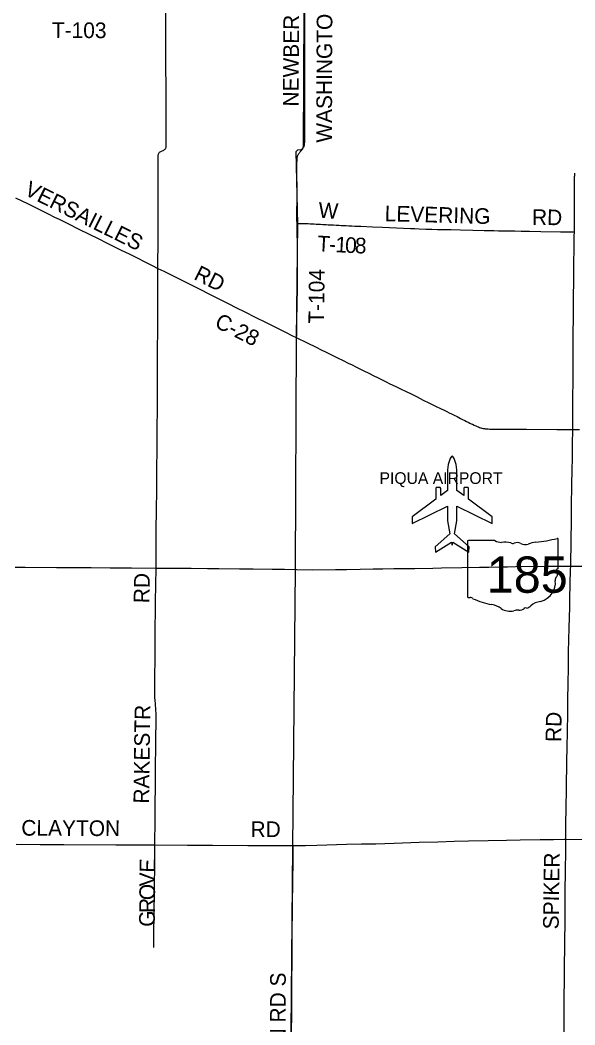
# Model space of a CAD drawing. Extents: x -87 to 2145, y -2128 to 440.
# Drawn here: x 168 to 221.2, y -563.5 to -467.2 of the extents above; entities that cross this region are included whole.
import ezdxf

# ---------------------------------------------------------------- set-up
doc = ezdxf.new("R2010")
doc.units = 0
for name, color, linetype in [('GM_X_Airport_Class_2', 7, 'Continuous'), ('GM_X_Airport_Location_Class_2', 7, 'Continuous'), ('GM_X_Airport_Text_Class_2', 7, 'Continuous'), ('GM_X_County_Road', 7, 'Continuous'), ('GM_X_County_Road_Text', 7, 'Continuous'), ('GM_X_State_Location', 7, 'Continuous'), ('GM_X_State_Route', 7, 'Continuous'), ('GM_X_State_Shield', 7, 'Continuous'), ('GM_X_Township', 7, 'Continuous'), ('GM_X_Township_Road', 7, 'Continuous'), ('GM_X_Township_Road_Text', 7, 'Continuous')]:
    doc.layers.add(name, color=color, linetype=linetype)

msp = doc.modelspace()

# ---------------------------------------------------------------- linework, layer by layer
at = {"layer": 'GM_X_Airport_Class_2'}
msp.add_lwpolyline([(207.876, -513.109), (205.594, -514.797), (205.594, -515.444), (208.989, -513.771), (208.989, -515.18), (209.214, -516.427), (207.817, -517.68), (207.839, -518.196), (209.369, -517.248), (209.44, -517.525), (209.51, -517.248), (211.041, -518.196), (211.062, -517.68), (209.665, -516.427), (209.891, -515.18), (209.891, -513.771), (213.286, -515.444), (213.286, -514.797), (211.004, -513.109), (211.004, -512.102), (210.968, -511.98), (210.58, -511.98), (210.544, -512.102), (210.544, -512.77), (209.891, -512.286), (209.891, -512.286), (209.891, -510.297), (209.825, -509.771), (209.77, -509.584), (209.635, -509.2), (209.511, -509.03), (209.44, -509), (209.369, -509.03), (209.244, -509.2), (209.109, -509.584), (209.055, -509.771), (208.989, -510.297), (208.989, -512.286), (208.335, -512.77), (208.335, -512.102), (208.3, -511.98), (207.911, -511.98), (207.876, -512.102)], close=True, dxfattribs=at)
at = {"layer": 'GM_X_Airport_Location_Class_2'}
msp.add_line((209.44, -513.913), (209.44, -513.913), dxfattribs=at)
at = {"layer": 'GM_X_County_Road'}
for points in [[(181.247, -490.98), (181.253, -488.079), (181.261, -485.553), (181.257, -484.307), (181.26, -482.912), (181.256, -481.01), (181.263, -480.221), (181.271, -480.121), (181.284, -480.054), (181.306, -479.989), (181.337, -479.926), (181.366, -479.883), (181.402, -479.844), (181.443, -479.811), (181.531, -479.761), (181.797, -479.634), (181.878, -479.584), (181.929, -479.535), (181.959, -479.494), (181.983, -479.452), (181.998, -479.418), (182.02, -479.336), (182.032, -479.258), (182.042, -479.112), (182.043, -478.916), (182.029, -476.881), (182.021, -475.733), (182.019, -474.65), (182.018, -473.322), (182.014, -471.878), (182.01, -469.992), (182.003, -467.974), (182.002, -466.354)], [(167.595, -484.197), (168.815, -484.802), (169.506, -485.143), (170.713, -485.737), (171.345, -486.051), (171.77, -486.265), (172.604, -486.687), (173.677, -487.218), (175.573, -488.157), (176.323, -488.529), (177.13, -488.931), (177.66, -489.192), (178.543, -489.627), (180.684, -490.7), (181.247, -490.98)], [(181.057, -519.724), (181.064, -519.155), (181.086, -517.073), (181.085, -515.647), (181.098, -514.58), (181.129, -511.842), (181.151, -509.874), (181.163, -508.677), (181.182, -506.43), (181.194, -504.331), (181.2, -502.839), (181.203, -501.461), (181.21, -499.608), (181.212, -498.509), (181.216, -497.148), (181.226, -494.999), (181.247, -490.98)], [(181.247, -490.98), (181.8, -491.255), (183.899, -492.304), (185.322, -493.015), (186.127, -493.423), (186.818, -493.763), (187.975, -494.348), (188.767, -494.745), (189.512, -495.125), (190.627, -495.682), (191.536, -496.138), (191.932, -496.336), (192.636, -496.689), (193.46, -497.095), (194.077, -497.4), (194.5, -497.597)], [(194.5, -497.597), (195.532, -498.122), (196.39, -498.544), (196.876, -498.783), (197.358, -499.019), (197.927, -499.299), (198.439, -499.551), (198.999, -499.826), (199.465, -500.059), (199.841, -500.243), (200.19, -500.414), (200.524, -500.582), (200.919, -500.775), (201.521, -501.071), (201.939, -501.278), (202.27, -501.444), (202.731, -501.671), (203.116, -501.86), (203.477, -502.037), (203.981, -502.281), (204.496, -502.53), (205.025, -502.791), (205.494, -503.019), (206.067, -503.303), (206.668, -503.6), (207.202, -503.861), (207.905, -504.208), (208.324, -504.414), (208.673, -504.586), (208.91, -504.703), (209.146, -504.822), (209.368, -504.933), (209.615, -505.055), (209.904, -505.197), (210.247, -505.367), (210.438, -505.462), (210.643, -505.566), (210.804, -505.647), (210.969, -505.729), (211.134, -505.809), (211.269, -505.872), (211.394, -505.933), (211.549, -506.005), (211.698, -506.074), (211.84, -506.139), (211.948, -506.185), (212.051, -506.226), (212.137, -506.256), (212.22, -506.283), (212.295, -506.302), (212.377, -506.321), (212.452, -506.335), (212.537, -506.348), (212.608, -506.356), (212.679, -506.363), (212.755, -506.369), (212.892, -506.376), (213.044, -506.382), (213.189, -506.387), (213.354, -506.391), (213.48, -506.393), (213.616, -506.395), (213.799, -506.398), (214.68, -506.398), (215.672, -506.404), (216.573, -506.41), (219.471, -506.422), (220.075, -506.428), (220.619, -506.434), (220.99, -506.435)], [(220.99, -506.435), (221.653, -506.434)], [(180.955, -546.275), (180.971, -543.83), (180.986, -542.321), (181.009, -540.714), (181.023, -539.32), (181.053, -536.253), (181.082, -534.251), (181.085, -534.04), (181.077, -533.724), (181.043, -533.273), (180.998, -532.766), (180.972, -532.373), (180.96, -532.174), (180.954, -531.979), (180.955, -530.338), (180.969, -528.239), (180.972, -527.091), (180.988, -525.926), (181.007, -523.386), (181.015, -522.91), (181.057, -519.724)], [(167.652, -546.192), (169.949, -546.22), (172.213, -546.238), (177.217, -546.26), (178.857, -546.267), (180.955, -546.275)], [(180.842, -556.093), (180.848, -554.966), (180.858, -554.195), (180.869, -553.441), (180.878, -552.506), (180.905, -551.096), (180.922, -550.259), (180.941, -548.225), (180.955, -546.275)], [(180.955, -546.275), (184.09, -546.294), (186.469, -546.305), (189.848, -546.326), (192.67, -546.339), (194.215, -546.331)], [(194.215, -546.331), (195.398, -546.311), (196.48, -546.287), (199.315, -546.213), (200.749, -546.176), (202.136, -546.152), (202.988, -546.127), (203.87, -546.096), (206.283, -546.014), (208.078, -545.959), (209.632, -545.923), (210.999, -545.888), (212.881, -545.849), (214.634, -545.814), (215.94, -545.794), (217.885, -545.749), (219.135, -545.736)], [(219.135, -545.736), (220.192, -545.725), (220.323, -545.724)], [(220.323, -545.724), (225.107, -545.736), (225.258, -545.737)]]:
    msp.add_lwpolyline(points, dxfattribs=at)
at = {"layer": 'GM_X_State_Route'}
msp.add_lwpolyline([(167.557, -519.62), (168.513, -519.626), (171.515, -519.654), (174.844, -519.674), (176.648, -519.684), (177.403, -519.692), (178.715, -519.698), (181.057, -519.724), (181.169, -519.724), (182.202, -519.724), (183.799, -519.741), (184.435, -519.743), (186.004, -519.752), (187.087, -519.756), (189.042, -519.778), (190.363, -519.793), (192.178, -519.821), (193.371, -519.839), (194.505, -519.855), (194.55, -519.856), (196.099, -519.875), (198.263, -519.854), (199.313, -519.841), (200.617, -519.819), (201.876, -519.804), (202.785, -519.793), (203.831, -519.773), (204.817, -519.761), (205.854, -519.747), (207.581, -519.717), (208.413, -519.698), (210.374, -519.658), (212.056, -519.63), (212.961, -519.617), (213.981, -519.606), (214.749, -519.591), (215.509, -519.58), (218.534, -519.548), (220.294, -519.53), (220.795, -519.527), (222.646, -519.528)], dxfattribs=at)
at = {"layer": 'GM_X_State_Shield'}
for p, q in [((210.902, -517.177), (210.902, -522.461)), ((213.535, -517.087), (210.987, -517.087)), ((219.603, -519.719), (219.603, -516.956)), ((219.602, -519.719), (219.603, -519.719))]:
    msp.add_line(p, q, dxfattribs=at)
for centre, major_axis, start_param, end_param in [((211.001, -517.166), (0.101, 0), 1.712693, 3.28349), ((214.142, -516.473), (0.978, 0), 4.042523, 4.731795), ((214.466, -520.053), (3.51, 0), 1.404758, 1.657858), ((215.263, -517.139), (0.282, 0), 3.836095, 5.185415), ((215.677, -517.749), (0.586, 0), 0.950623, 2.079405), ((216.434, -516.912), (0.705, 0), 4.081561, 5.145723), ((217.68, -518.7), (1.856, 0), 1.699011, 2.107814), ((216.503, -509.884), (9.227, 0), 4.814394, 5.042369), ((219.506, -516.944), (0.0969, 0), 6.141152, 7.989035), ((219.58, -519.922), (0.15, 0), 1.883978, 3.671073), ((218.627, -520.272), (0.9, 0), 5.934695, 6.695948), ((219.499, -519.73), (0.104, 0), 5.05454, 6.418171), ((217.02, -521.227), (2.308, 0), 5.101752, 6.440018), ((219.95, -520.876), (0.655, 0), 2.387724, 3.262537), ((211.002, -522.472), (0.102, 0), 3.00124, 4.508301), ((211.018, -521.932), (0.776, 0), 4.665946, 4.897461), ((211.176, -522.765), (0.28, 0), 0.519207, 1.627899), ((214.709, -518.019), (6.663, 0), 4.195997, 4.488961), ((212.723, -524.834), (2.085, 0), 0.823519, 1.323587), ((217.993, -523.944), (1.264, 0), 1.647645, 2.488434), ((214.978, -522.792), (1.323, 0), 4.026481, 4.996735), ((215.742, -524.618), (1.087, 0), 1.495662, 1.94098), ((215.839, -523.187), (0.705, 0), 4.691044, 5.507374), ((216.476, -523.699), (0.198, 0), 1.147584, 2.315152), ((216.392, -522.973), (0.746, 0), 4.937069, 5.64225)]:
    msp.add_ellipse(centre, major_axis=major_axis, ratio=0.8, start_param=start_param, end_param=end_param, dxfattribs=at)
at = {"layer": 'GM_X_Township'}
for points in [[(90.326, -451.873), (90.326, -638.912), (100.953, -639.016), (111.479, -639.144), (114.255, -639.152), (127.218, -639.312), (140.406, -639.325), (142.807, -639.317), (144.927, -639.27), (178.921, -639.673), (180.382, -639.676), (193.831, -639.58), (193.148, -599.226), (193.87, -578.272), (194.163, -546.477), (194.423, -519.843), (194.535, -497.733), (194.66, -486.734), (194.487, -479.781), (194.661, -479.612), (194.97, -479.59), (195.138, -479.475), (195.194, -479.257), (195.32, -453.117)], [(245.085, -639.383), (219.087, -639.346), (193.831, -639.58), (193.605, -626.197), (193.148, -599.226), (193.87, -578.272), (194.163, -546.477), (194.423, -519.843), (194.535, -497.733), (194.66, -486.734), (194.487, -479.781), (194.661, -479.612), (194.97, -479.59), (195.138, -479.475), (195.194, -479.257), (195.32, -453.117)]]:
    msp.add_lwpolyline(points, dxfattribs=at)
at = {"layer": 'GM_X_Township_Road'}
for points in [[(194.571, -486.669), (194.569, -486.587), (194.567, -486.422), (194.567, -486.177), (194.565, -485.865), (194.569, -484.077), (194.571, -482.978), (194.566, -482.321), (194.564, -481.633), (194.564, -481.13), (194.567, -480.754), (194.569, -480.661), (194.571, -480.568), (194.573, -480.485), (194.578, -480.424), (194.582, -480.368), (194.591, -480.311), (194.601, -480.264), (194.617, -480.22), (194.638, -480.159), (194.662, -480.107), (194.687, -480.059), (194.712, -480.016), (194.74, -479.973), (194.775, -479.925), (194.808, -479.884), (194.855, -479.823), (194.899, -479.771), (194.946, -479.712), (194.99, -479.658), (195.04, -479.593), (195.081, -479.539), (195.129, -479.474), (195.17, -479.413), (195.203, -479.363), (195.224, -479.326), (195.242, -479.291), (195.259, -479.246), (195.27, -479.207), (195.281, -479.161), (195.289, -479.118), (195.298, -479.059), (195.302, -479.011), (195.302, -478.97), (195.304, -478.918), (195.307, -478.864), (195.31, -478.788), (195.311, -478.688), (195.311, -478.582), (195.311, -478.306), (195.313, -476.654), (195.314, -474.456), (195.325, -472.193), (195.325, -470.339), (195.333, -467.944), (195.333, -467.19), (195.356, -465.812)], [(221.147, -487.479), (221.149, -487.354), (221.153, -486.831), (221.15, -485.29), (221.166, -483.275), (221.164, -482.769), (221.166, -482.599), (221.166, -482.48), (221.169, -482.357), (221.171, -482.261), (221.175, -482.163), (221.181, -482.057), (221.188, -481.964), (221.2, -481.844)], [(194.5, -497.597), (194.53, -497.503), (194.539, -497.461), (194.545, -497.419), (194.551, -497.353), (194.556, -497.271), (194.562, -496.776), (194.562, -495.984), (194.588, -494.456), (194.608, -492.848), (194.621, -491.32), (194.619, -490.047), (194.618, -489.226), (194.614, -488.914), (194.61, -488.567), (194.603, -488.219), (194.597, -487.935), (194.592, -487.619), (194.588, -487.416), (194.584, -487.219), (194.578, -486.978), (194.572, -486.766), (194.571, -486.669)], [(194.571, -486.669), (194.665, -486.668), (194.78, -486.668), (194.919, -486.665), (195.073, -486.67), (195.262, -486.676), (195.451, -486.681), (195.642, -486.687), (195.82, -486.694), (195.998, -486.702), (196.208, -486.713), (196.408, -486.724), (196.621, -486.737), (196.833, -486.75), (197.029, -486.761), (197.172, -486.77), (197.356, -486.78), (197.547, -486.791), (197.766, -486.802), (198.06, -486.816), (198.318, -486.828), (198.595, -486.843), (198.814, -486.854), (199.062, -486.867), (199.281, -486.878), (199.537, -486.891), (199.817, -486.904), (200.104, -486.917), (200.375, -486.928), (200.683, -486.941), (201.807, -486.991), (202.766, -487.034), (205.451, -487.149), (205.644, -487.158), (205.872, -487.167), (206.265, -487.182), (206.905, -487.203), (207.504, -487.221), (208.04, -487.236), (208.726, -487.251), (209.311, -487.262), (210.245, -487.277), (211.43, -487.308), (212.508, -487.336), (212.955, -487.349), (213.437, -487.358), (213.862, -487.362), (214.275, -487.369), (214.73, -487.375), (215.445, -487.384), (216.035, -487.393), (216.833, -487.405), (217.944, -487.427), (219.824, -487.462), (221.147, -487.479)], [(220.99, -506.435), (220.996, -505.423), (221.005, -504.422), (221.016, -503.472), (221.012, -502.8), (221.02, -502.34), (221.025, -501.799), (221.03, -501.487), (221.035, -501.062), (221.037, -500.554), (221.034, -499.866), (221.035, -499.423), (221.039, -497.997), (221.044, -497.08), (221.067, -495.837), (221.06, -494.733), (221.067, -493.619), (221.084, -492.287), (221.108, -490.586), (221.119, -488.975), (221.14, -487.873), (221.147, -487.479)], [(220.795, -519.527), (220.838, -517.022), (220.867, -515.251), (220.887, -513.874), (220.909, -511.641), (220.932, -510.397), (220.958, -509.102), (220.974, -507.832), (220.99, -506.435)], [(220.323, -545.724), (220.319, -545.308), (220.336, -544.004), (220.351, -542.986), (220.396, -540.634), (220.438, -538.42), (220.468, -536.727), (220.483, -535.599), (220.522, -533.485), (220.535, -532.268), (220.553, -530.896), (220.574, -529.156), (220.6, -527.754), (220.659, -525.464), (220.706, -523.467), (220.722, -522.63), (220.789, -519.844), (220.795, -519.527)], [(194.019, -578.178), (194.027, -577.71), (194.032, -576.858), (194.033, -576.136), (194.035, -574.593), (194.033, -572.935), (194.035, -572.281), (194.04, -571.493), (194.04, -570.472), (194.047, -566.916), (194.05, -564.143), (194.063, -562.585), (194.069, -561.354), (194.077, -559.845), (194.1, -556.889), (194.117, -555.268), (194.15, -551.867), (194.17, -549.951), (194.198, -547.603), (194.215, -546.331)], [(220.196, -558.95), (220.208, -558.364), (220.205, -557.613), (220.218, -556.313), (220.234, -555.393), (220.253, -553.78), (220.262, -552.059), (220.275, -551.124), (220.303, -548.388), (220.316, -547.203), (220.325, -545.874), (220.323, -545.724)], [(220.134, -566.906), (220.135, -566.213), (220.152, -564.849), (220.161, -563.8), (220.172, -562.21), (220.181, -560.571), (220.192, -559.538), (220.196, -558.95)]]:
    msp.add_lwpolyline(points, dxfattribs=at)

# ---------------------------------------------------------------- texts
at = {"layer": 'GM_X_Airport_Text_Class_2'}
msp.add_text('PIQUA AIRPORT', height=1.125, rotation=0.00001, dxfattribs=at).set_placement((202.477, -511.654))
at = {"layer": 'GM_X_County_Road_Text'}
for s, rotation, p in [('VERSAILLES', 333.5356, (168.336, -483.869)), ('RD', 333.43495, (184.584, -491.972)), ('C-28', 333.43553, (186.574, -496.551)), ('RD', 89.01607, (180.415, -523.1)), ('RAKESTR', 89.25048, (180.393, -542.314)), ('CLAYTON', 359.71236, (168.146, -545.379)), ('RD', 0.00001, (190.113, -545.516)), ('E', 88.68849, (180.975, -548.941)), ('V', 89.55192, (180.965, -550.255)), ('O', 89.57742, (180.955, -551.574)), ('R', 89.5831, (180.946, -552.806)), ('G', 89.57742, (180.936, -554.126))]:
    msp.add_text(s, height=1.5, rotation=rotation, dxfattribs=at).set_placement(p)
at = {"layer": 'GM_X_State_Location'}
for s in ['s', 'r']:
    msp.add_text(s, height=0.005, dxfattribs=at).set_placement((215.154, -520.17))
msp.add_text('185', height=0.005, rotation=0.00001, dxfattribs=at).set_placement((213.389, -520.534))
at = {"layer": 'GM_X_State_Shield'}
msp.add_text('185', height=3.4805, dxfattribs=at).set_placement((212.747, -522.088))
at = {"layer": 'GM_X_Township_Road_Text'}
for s, rotation, p in [('WASHINGTON RD N', 89.7804, (197.911, -478.927)), ('NEWBERRY', 89.63219, (194.715, -475.462)), ('T-103', 359.7193, (171.071, -468.871)), ('W', 356.37589, (196.582, -486.118)), ('LEVERING', 358.41151, (202.954, -486.446)), ('RD', 359.01276, (217.073, -486.798)), ('T', 356.87842, (196.481, -489.326)), ('1', 356.94233, (198.218, -489.42)), ('0', 357.13734, (199.146, -489.47)), ('8', 357.91224, (200.091, -489.517)), ('-', 356.89234, (197.602, -489.387)), ('T-104', 89.43619, (197.161, -496.286)), ('RD', 89.01673, (219.883, -536.41)), ('SPIKER', 89.22482, (219.641, -554.372)), ('WASHINGTON RD S', 89.85158, (193.445, -577.679))]:
    msp.add_text(s, height=1.5, rotation=rotation, dxfattribs=at).set_placement(p)

doc.saveas('drawing.dxf')
